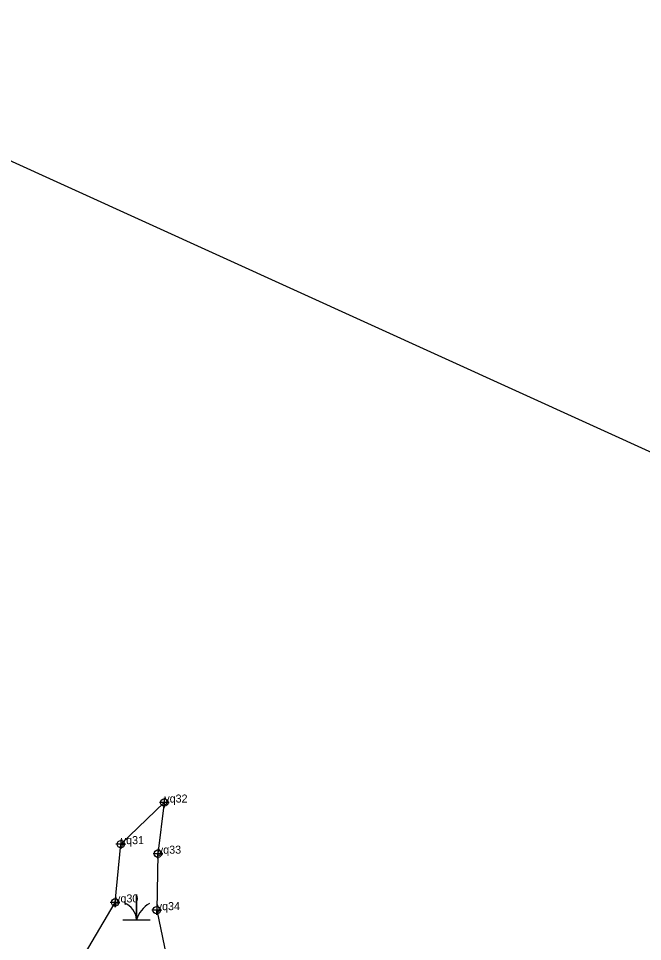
# Model space of a CAD drawing. Extents: x 2071991 to 2268989, y 436479 to 469629.
# Drawn here: x 2247145 to 2247535, y 439790 to 440367 of the extents above; entities that cross this region are included whole.
import ezdxf

# ---------------------------------------------------------------- set-up
doc = ezdxf.new("R2010")
doc.units = 0
for name, color, linetype in [('approx_PSA', 7, 'Continuous'), ('Exist Environmental Wetland Boundary', 7, 'Continuous'), ('Exist Environmental Wetland Boundary Cogo Comment', 7, 'Continuous'), ('Exist Environmental Wetland Boundary Cogo Point CELL', 7, 'Continuous'), ('Exist Hydro Swamp or Marsh', 7, 'Continuous')]:
    doc.layers.add(name, color=color, linetype=linetype)

msp = doc.modelspace()

# ---------------------------------------------------------------- linework, layer by layer
at = {"layer": 'approx_PSA'}
msp.add_line((2245698.16, 440932.68), (2248718.76, 439560.51), dxfattribs=at)
at = {"layer": 'Exist Environmental Wetland Boundary'}
msp.add_lwpolyline([(2247186.02, 439782.21), (2247205.24, 439814.66), (2247208.78, 439851.06), (2247236, 439877.04), (2247231.99, 439845.1), (2247231.25, 439809.83), (2247239.7, 439769.66)], dxfattribs=at)
at = {"layer": 'Exist Environmental Wetland Boundary Cogo Point CELL'}
for points in [[(2247236, 439880.04), (2247236, 439874.04), (2247236, 439877.04), (2247239, 439877.04), (2247233, 439877.04)], [(2247208.78, 439854.06), (2247208.78, 439848.06), (2247208.78, 439851.06), (2247211.78, 439851.06), (2247205.78, 439851.06)], [(2247231.99, 439848.1), (2247231.99, 439842.1), (2247231.99, 439845.1), (2247234.99, 439845.1), (2247228.99, 439845.1)], [(2247205.24, 439817.66), (2247205.24, 439811.66), (2247205.24, 439814.66), (2247208.24, 439814.66), (2247202.24, 439814.66)], [(2247231.25, 439812.83), (2247231.25, 439806.83), (2247231.25, 439809.83), (2247234.25, 439809.83), (2247228.25, 439809.83)]]:
    msp.add_lwpolyline(points, dxfattribs=at)
for centre in [(2247236, 439877.04), (2247208.78, 439851.06), (2247231.99, 439845.1), (2247205.24, 439814.66), (2247231.25, 439809.83)]:
    msp.add_circle(centre, 2.34, dxfattribs=at)
at = {"layer": 'Exist Hydro Swamp or Marsh'}
msp.add_lwpolyline([(2247210.02, 439803.88), (2247218.62, 439803.88), (2247218.62, 439819.66), (2247218.62, 439803.88), (2247227.22, 439803.88)], dxfattribs=at)
for centre, radius, start, end in [((2247206.36, 439802.99), 12.3, 4.14034, 67.53497), ((2247236.86, 439797.81), 19.22, 122.12745, 161.62219)]:
    msp.add_arc(centre, radius, start, end, dxfattribs=at)

# ---------------------------------------------------------------- texts
at = {"layer": 'Exist Environmental Wetland Boundary Cogo Comment'}
for s, p in [('yq32', (2247236, 439877.04)), ('yq31', (2247208.78, 439851.06)), ('yq33', (2247231.99, 439845.1)), ('yq30', (2247205.24, 439814.66)), ('yq34', (2247231.25, 439809.83))]:
    msp.add_text(s, height=5, dxfattribs=at).set_placement(p)

doc.saveas('drawing.dxf')
